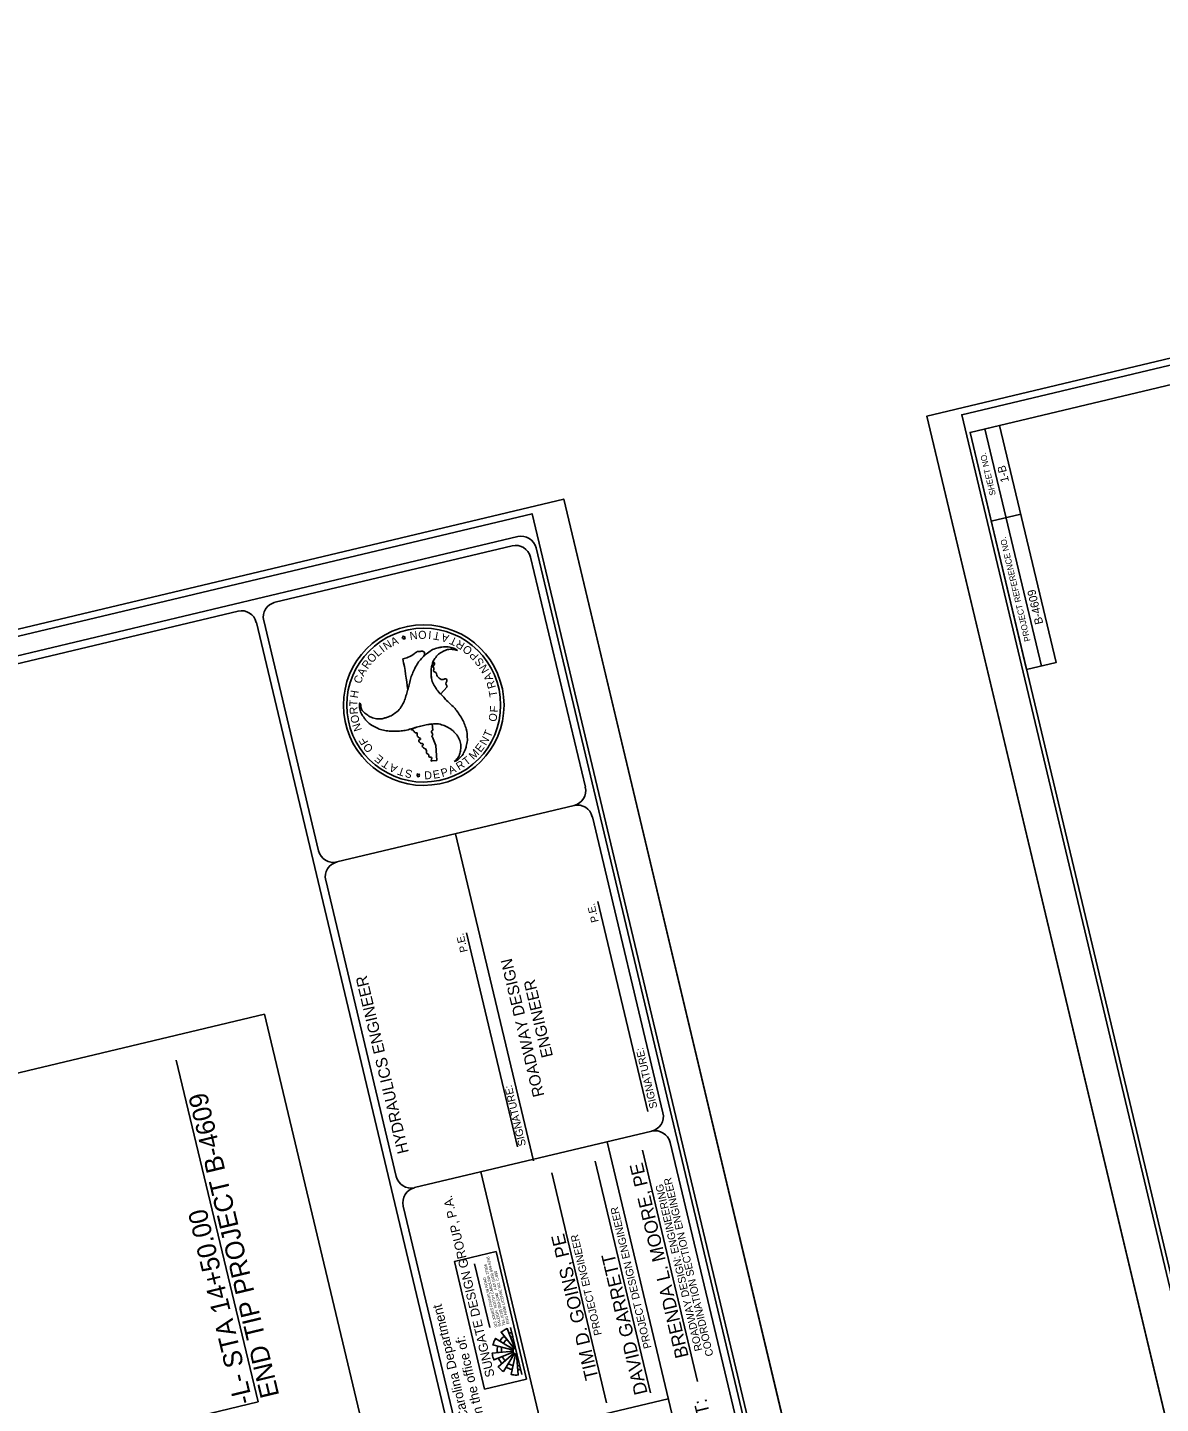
# Model space of a CAD drawing. Extents: x 1734738 to 1742883, y 698103 to 703125.
# Drawn here: x 1736174 to 1737661, y 700702 to 702508 of the extents above; entities that cross this region are included whole.
import ezdxf

# ---------------------------------------------------------------- set-up
doc = ezdxf.new("R2010")
doc.units = 0
for name, color, linetype in [('Exist Cultural Recreational Athletic Track', 7, 'Continuous'), ('Exist Map Preparation Border Sheet 1 CELL', 7, 'Continuous'), ('Exist Road Primary Interstate Shield CELL', 7, 'Continuous'), ('Exist Road Primary US Shield CELL', 7, 'Continuous'), ('Exist Road Primary US Structure Standard Bridge Number Label', 7, 'Continuous'), ('Exist Road Secondary Structure Pipe Number Label', 7, 'Continuous'), ('Exist Road Secondary Type 41 SR Number Label', 7, 'Continuous'), ('Exist Road Secondary Type 51 Divided Label', 7, 'Continuous'), ('Exist Road Secondary Type 51 Number Label', 7, 'Continuous')]:
    doc.layers.add(name, color=color, linetype=linetype)

msp = doc.modelspace()

# ---------------------------------------------------------------- linework, layer by layer
at = {"layer": 'Exist Cultural Recreational Athletic Track'}
for p in [(1736369.4, 701152.2), (1736188.7, 700634.5)]:
    msp.add_line(p, (1736477, 700703.7), dxfattribs=at)
at = {"layer": 'Exist Road Primary Interstate Shield CELL'}
for p, q in [((1737505.1, 701669.7), (1737430.9, 701981.1)), ((1737524.6, 701674.4), (1737450.3, 701985.7)), ((1737439.3, 701859.7), (1737478.2, 701869))]:
    msp.add_line(p, q, dxfattribs=at)
for points in [[(1737411.4, 701976.4), (1738106.9, 699058.2), (1740147.7, 699544.6), (1739452.2, 702462.8)], [(1737485.6, 701665.1), (1737411.4, 701976.4), (1737450.3, 701985.7), (1737524.6, 701674.4)]]:
    msp.add_lwpolyline(points, close=True, dxfattribs=at)
at = {"layer": 'Exist Road Primary US Shield CELL'}
msp.add_lwpolyline([(1735867.2, 699650.6), (1736804.2, 699873.9), (1736485.1, 701212.6), (1735736.8, 701034.2), (1735787.7, 700820.7), (1735599, 700775.7)], close=True, dxfattribs=at)
at = {"layer": 'Exist Road Primary US Structure Standard Bridge Number Label'}
for p, q in [((1737354.8, 701997.9), (1738135.7, 698721.7)), ((1737658.8, 698612.7), (1736878, 701888.9))]:
    msp.add_line(p, q, dxfattribs=at)
at = {"layer": 'Exist Road Secondary Structure Pipe Number Label'}
for points in [[(1740226.1, 699246.6), (1739453.3, 702488.8), (1737400.6, 701999.6), (1738173.4, 698757.4)], [(1737609.2, 698627.6), (1736836.4, 701869.7), (1734783.7, 701380.5), (1735556.5, 698138.3)]]:
    msp.add_lwpolyline(points, close=True, dxfattribs=at)
at = {"layer": 'Exist Road Secondary Type 41 SR Number Label'}
for points in [[(1740275.8, 699231.7), (1739494.9, 702508), (1737354.8, 701997.9), (1738135.7, 698721.7)], [(1734738, 701378.8), (1735518.8, 698102.6), (1737658.8, 698612.7), (1736878, 701888.9)]]:
    msp.add_lwpolyline(points, close=True, dxfattribs=at)
at = {"layer": 'Exist Road Secondary Type 51 Divided Label'}
for p, q in [((1737133, 698964.3), (1736474.5, 701727)), ((1736556.2, 701427.3), (1736484.3, 701729.3)), ((1736683.5, 701723.3), (1736683.5, 701723.3)), ((1736667.2, 701707.4), (1736665.6, 701706.6)), ((1736665.6, 701706.6), (1736667.3, 701706.2)), ((1736668.2, 701707.8), (1736667, 701709.2)), ((1736667, 701709.2), (1736667.2, 701707.4)), ((1736667.3, 701706.2), (1736667.5, 701704.4)), ((1736667.5, 701704.4), (1736668.4, 701706)), ((1736669.9, 701708.5), (1736668.2, 701707.8)), ((1736668.4, 701706), (1736670.2, 701705.7)), ((1736669, 701707), (1736669.9, 701708.5)), ((1736670.2, 701705.7), (1736669, 701707)), ((1736673.3, 701638.8), (1736673.3, 701638.8)), ((1736725.1, 701642.6), (1736716.4, 701632.8)), ((1736716.4, 701632.8), (1736716.4, 701632.8)), ((1736610, 701621), (1736610.2, 701620.9)), ((1736610, 701621), (1736610.2, 701620.9)), ((1736705.5, 701593.7), (1736706.2, 701585.4)), ((1736705.8, 701576.5), (1736710.3, 701565.5)), ((1736710.3, 701565.5), (1736711.6, 701545.5)), ((1736711.6, 701545.5), (1736705.3, 701545.1)), ((1736684.6, 701525.9), (1736686.2, 701526.7)), ((1736686.4, 701525.6), (1736684.6, 701525.9)), ((1736686.2, 701526.7), (1736686.1, 701528.5)), ((1736686.1, 701528.5), (1736687.3, 701527.1)), ((1736686.5, 701523.8), (1736686.4, 701525.6)), ((1736687.5, 701525.3), (1736686.5, 701523.8)), ((1736687.3, 701527.1), (1736689, 701527.9)), ((1736689.3, 701525), (1736687.5, 701525.3)), ((1736689, 701527.9), (1736688, 701526.3)), ((1736688, 701526.3), (1736689.3, 701525)), ((1736891.6, 701486.6), (1736580.3, 701412.5)), ((1736838.3, 701020.2), (1736735.9, 701449.5)), ((1736658.1, 700999.7), (1736565.5, 701388.4)), ((1736988.4, 701085.1), (1736922.9, 701360.4)), ((1736817.4, 701038.7), (1736750.5, 701319.3)), ((1736993.5, 701059.1), (1736682.3, 700984.9)), ((1737076.3, 700451.7), (1736934.9, 701045.1)), ((1737053.8, 700730.3), (1736981.3, 701034.3)), ((1736991.8, 700715.5), (1736919.4, 701019.5)), ((1736769.3, 701005.6), (1736910.7, 700412.3)), ((1736934.1, 700702.5), (1736862.2, 701004.3)), ((1736799.6, 700406.3), (1736667.4, 700960.8)), ((1736849.7, 700668.2), (1737015.3, 700707.7))]:
    msp.add_line(p, q, dxfattribs=at)
for points in [[(1736817.8, 701839.6), (1734813.9, 701362)], [(1736810.4, 701827.6), (1736499.1, 701753.4)], [(1736906.4, 701510.7), (1736834.5, 701812.7)], [(1737528.2, 698945.4), (1736841.9, 701824.8)], [(1736450.5, 701741.8), (1734825.9, 701354.6)], [(1737008.3, 701083.2), (1736915.7, 701471.8)], [(1737149.8, 700489.8), (1737017.6, 701044.3)]]:
    msp.add_lwpolyline(points, dxfattribs=at)
for centre, radius, start, end in [((1736814.9, 701808.1), 20, 13.4059, 103.4059), ((1736822.3, 701820.1), 20, 13.4059, 103.4059), ((1736455, 701722.3), 20, 13.4059, 103.4059), ((1736503.6, 701733.9), 20, 103.4059, 193.4059), ((1736694.2, 701618.4), 105.4, 95.827, 275.827), ((1736694.2, 701618.4), 105.4, 275.827, 95.827), ((1736694.2, 701618.4), 101, 275.827, 95.827), ((1736694.2, 701618.4), 101, 95.827, 275.827), ((1736121.5, 701571.6), 555.9, 6.9446, 11.1506), ((1736121.5, 701571.6), 555.9, 1.5055, 1.6051), ((1736886.9, 701506.1), 20, 283.4059, 13.4059), ((1736896.1, 701467.2), 20, 13.4059, 103.4059), ((1736575.7, 701431.9), 20, 193.4059, 283.4059), ((1736585, 701393), 20, 103.4059, 193.4059), ((1736988.8, 701078.5), 20, 283.4059, 13.4059), ((1736998.1, 701039.6), 20, 13.4059, 103.4059), ((1736677.5, 701004.3), 20, 193.4059, 283.4059), ((1736686.8, 700965.4), 20, 103.4059, 193.4059)]:
    msp.add_arc(centre, radius, start, end, dxfattribs=at)
for points in [[(1736738.5, 701690.1), (1736736.7, 701691.5), (1736730.2, 701694.2), (1736722.7, 701695), (1736722, 701695), (1736718, 701694.7), (1736713.3, 701693.7), (1736705.9, 701691.2), (1736699.2, 701686.8), (1736696.4, 701685), (1736693.8, 701682.3), (1736688.6, 701676.5), (1736684.6, 701670.4), (1736680.8, 701662.9), (1736677.9, 701656.1), (1736675.8, 701648.7), (1736674, 701641.3), (1736671.9, 701634.2), (1736669.8, 701626.7), (1736666.7, 701619.9), (1736666.4, 701619.3), (1736661.9, 701612.5), (1736656, 701607.4), (1736649.8, 701603.7), (1736646.5, 701602.4), (1736642.1, 701601.3), (1736639.6, 701600.5), (1736634.2, 701600.4), (1736626.9, 701601.8), (1736620.7, 701605), (1736615.7, 701609), (1736612.1, 701614.6), (1736610.2, 701620.9), (1736610, 701621)], [(1736666.9, 701679.1), (1736673.7, 701681.3), (1736681.6, 701685.8), (1736685.8, 701688.6), (1736689.7, 701689), (1736694.5, 701688.5), (1736695.4, 701684.1)], [(1736695.4, 701684.1), (1736693.8, 701682.3), (1736688.6, 701676.5), (1736684.6, 701670.4), (1736680.8, 701662.9), (1736677.9, 701656.1), (1736675.8, 701648.7), (1736674, 701641.3), (1736673.3, 701638.8)], [(1736734.3, 701544.3), (1736736.6, 701545.3), (1736742.1, 701549.6), (1736746.6, 701555.6), (1736746.8, 701556.2), (1736748.7, 701559.9), (1736750, 701564.3), (1736751.6, 701572.1), (1736751.1, 701580), (1736751, 701583.3), (1736749.9, 701587.1), (1736747.5, 701594.3), (1736744.3, 701600.8), (1736739.7, 701607.9), (1736735.3, 701613.8), (1736729.9, 701619.3), (1736724.3, 701624.6), (1736719.2, 701630), (1736713.9, 701635.6), (1736709.5, 701641.6), (1736709.1, 701642.3), (1736705.5, 701649.6), (1736704, 701657.1), (1736703.9, 701664.3), (1736704.3, 701668), (1736705.7, 701672.2), (1736706.2, 701674.8), (1736708.8, 701679.5), (1736713.6, 701685.1), (1736719.5, 701688.9), (1736725.6, 701691.2), (1736732.1, 701691.6), (1736738.5, 701690.1)], [(1736716.4, 701632.8), (1736713.9, 701635.6), (1736709.5, 701641.6), (1736709.1, 701642.3), (1736705.5, 701649.6), (1736704, 701657.1), (1736703.9, 701664.3), (1736704.3, 701668), (1736705.7, 701672.2), (1736706.2, 701674.6)], [(1736706.3, 701674.6), (1736708.2, 701673.8), (1736708.5, 701672.3), (1736706.6, 701669.3), (1736707.6, 701665.9), (1736706.9, 701664.3), (1736706.9, 701663.3), (1736710.3, 701661.1), (1736711.3, 701657.8), (1736715.9, 701652.8), (1736718.4, 701651.9), (1736723.3, 701652.9), (1736724.5, 701651.6), (1736724.4, 701650), (1736723.4, 701646.5), (1736725.1, 701642.6)], [(1736610.2, 701620.9), (1736609.9, 701618.4), (1736610.8, 701611.5), (1736613.8, 701604.6), (1736614.2, 701604.1), (1736616.5, 701600.7), (1736619.6, 701597.2), (1736625.6, 701592.1), (1736632.7, 701588.4), (1736635.7, 701587), (1736639.3, 701586), (1736646.9, 701584.5), (1736654.2, 701584), (1736662.6, 701584.4), (1736669.9, 701585.2), (1736677.3, 701587.2), (1736684.7, 701589.3), (1736692, 701591.1), (1736699.4, 701592.9), (1736706.9, 701593.7), (1736707.5, 701593.8), (1736715.7, 701593.2), (1736723, 701590.7), (1736729.3, 701587.2), (1736732.3, 701585), (1736735.4, 701581.7), (1736737.1, 701579.9), (1736740, 701575.4), (1736742.5, 701568.4), (1736742.8, 701561.3), (1736741.8, 701554.9), (1736738.9, 701549.1), (1736734.3, 701544.3)], [(1736677.1, 701587.2), (1736677.3, 701587.2), (1736684.7, 701589.3), (1736692, 701591.1), (1736699.4, 701592.9), (1736705.5, 701593.7)], [(1736705.3, 701545.1), (1736704.7, 701544.8), (1736703.9, 701545.8), (1736704.8, 701548.8), (1736703.4, 701550.2), (1736702.1, 701550), (1736700.8, 701551.1), (1736701, 701553.1), (1736698.4, 701554.7), (1736697.9, 701556.4), (1736697.5, 701559.9), (1736692.8, 701563.7), (1736692.4, 701565.4), (1736693.5, 701566), (1736693.6, 701567.1), (1736689.9, 701568.5), (1736689.4, 701568.9), (1736687.7, 701572.1), (1736688.3, 701573), (1736689.8, 701573.4), (1736690.1, 701573.9), (1736689.2, 701575), (1736687.2, 701576.2), (1736685.5, 701578.8), (1736685.5, 701581.9), (1736683, 701582.2), (1736680.2, 701585.5), (1736678.6, 701586.1), (1736677.1, 701586.2)], [(1736706.2, 701585.4), (1736704.8, 701584.5), (1736704.5, 701582.8), (1736705.9, 701580.7), (1736705.9, 701579.1), (1736704.8, 701577.1), (1736705.8, 701576.5)]]:
    msp.add_spline(points, degree=3, dxfattribs=at)
at = {"layer": 'Exist Road Secondary Type 51 Number Label'}
for p, q in [((1736780.8, 700801.1), (1736760.7, 700885.1)), ((1736822.9, 700739.8), (1736808.2, 700801.2)), ((1736814, 700774.3), (1736811.3, 700781)), ((1736796.7, 700775.4), (1736796.7, 700775.4)), ((1736811.5, 700770.1), (1736804.3, 700769.5)), ((1736811.6, 700771.5), (1736804.6, 700773.3)), ((1736811.8, 700769), (1736805, 700766.3)), ((1736805.9, 700776.4), (1736812.1, 700772.6)), ((1736812.5, 700767.8), (1736807.1, 700763)), ((1736813, 700773.7), (1736808.5, 700779.3)), ((1736809.6, 700760.9), (1736813.4, 700767)), ((1736810.4, 700776.9), (1736813, 700773.7)), ((1736814.7, 700766.5), (1736813.2, 700759.4)), ((1736815.9, 700766.4), (1736816.5, 700759.2)), ((1736800.9, 700757.7), (1736800.9, 700757.7)), ((1736813.6, 700761.3), (1736813.6, 700761.3)), ((1736817.5, 700748.2), (1736817.5, 700748.2))]:
    msp.add_line(p, q, dxfattribs=at)
for points in [[(1736774.2, 700720.5), (1736734.4, 700887.8), (1736789.2, 700900.9), (1736829.1, 700733.5)], [(1736813, 700773.7), (1736795.8, 700795.2), (1736797, 700796.1), (1736798.4, 700797), (1736800, 700798), (1736801.3, 700798.7), (1736803.8, 700799.8), (1736814, 700774.3)], [(1736811.6, 700771.5), (1736785, 700778.4), (1736785.6, 700780.5), (1736786.4, 700782.7), (1736787.1, 700784.2), (1736787.8, 700785.6), (1736788.6, 700786.9), (1736812.1, 700772.6)], [(1736794.2, 700783.5), (1736795, 700784.7), (1736795.9, 700785.9), (1736796.9, 700787.1), (1736798.4, 700788.6), (1736800, 700790), (1736803.4, 700785.7), (1736802.4, 700784.8), (1736801.2, 700783.6), (1736800.4, 700782.7), (1736799.8, 700781.8), (1736799, 700780.6)], [(1736806.3, 700793.6), (1736808.1, 700794.3), (1736809.7, 700794.7), (1736811, 700789.4), (1736809.7, 700789), (1736808.3, 700788.5)], [(1736811.8, 700769), (1736786.2, 700758.7), (1736785.6, 700760.4), (1736785, 700762.3), (1736784.7, 700763.9), (1736784.3, 700765.9), (1736784.1, 700767.7), (1736811.5, 700770.1)], [(1736790.7, 700768.3), (1736790.6, 700769.8), (1736790.6, 700771.6), (1736790.8, 700773.4), (1736791, 700775), (1736791.4, 700776.8), (1736796.8, 700775.4), (1736796.5, 700774.4), (1736796.3, 700773.1), (1736796.1, 700771.2), (1736796.1, 700770), (1736796.2, 700768.8)], [(1736813.4, 700767), (1736798.9, 700743.7), (1736797.4, 700744.6), (1736795.9, 700745.8), (1736794.5, 700746.9), (1736793.1, 700748.3), (1736791.8, 700749.6), (1736812.5, 700767.8)], [(1736796.8, 700754), (1736796, 700755), (1736794.8, 700756.6), (1736793.7, 700758.3), (1736792.9, 700759.9), (1736792.4, 700761.2), (1736797.5, 700763.3), (1736798, 700762.1), (1736798.6, 700761), (1736799.3, 700759.8), (1736800.1, 700758.7), (1736801, 700757.6)], [(1736815.9, 700766.4), (1736818.3, 700739), (1736816.6, 700738.9), (1736814.1, 700738.9), (1736812.6, 700739), (1736810.6, 700739.3), (1736809.1, 700739.6), (1736814.7, 700766.5)], [(1736816.5, 700766.5), (1736816.2, 700766.5), (1736815.9, 700766.4), (1736815.2, 700766.4), (1736814.7, 700766.5), (1736814.3, 700766.6), (1736813.9, 700766.7), (1736813.6, 700766.9), (1736813.4, 700767), (1736812.9, 700767.4), (1736812.5, 700767.8), (1736812.2, 700768.1), (1736812, 700768.4), (1736811.9, 700768.7), (1736811.8, 700769), (1736811.6, 700769.5), (1736811.5, 700770.1), (1736811.5, 700770.5), (1736811.5, 700770.8), (1736811.5, 700771.1), (1736811.6, 700771.5), (1736811.8, 700772.1), (1736812.1, 700772.6), (1736812.2, 700772.9), (1736812.5, 700773.2), (1736812.7, 700773.4), (1736813, 700773.7), (1736813.5, 700774), (1736814, 700774.3), (1736814.3, 700774.4), (1736814.6, 700774.4)], [(1736810.5, 700746.1), (1736808.9, 700746.4), (1736807.7, 700746.8), (1736806.3, 700747.3), (1736805.1, 700747.8), (1736803.8, 700748.5), (1736802.4, 700749.3), (1736805.3, 700754), (1736806.5, 700753.3), (1736807.5, 700752.8), (1736808.6, 700752.3), (1736809.8, 700751.9), (1736810.8, 700751.7), (1736811.6, 700751.5)], [(1736821.3, 700746.2), (1736820.3, 700746), (1736819, 700745.8), (1736817.7, 700745.6), (1736817.2, 700751.1), (1736818.2, 700751.2), (1736819.1, 700751.4), (1736820, 700751.6)]]:
    msp.add_lwpolyline(points, close=True, dxfattribs=at)
for start, end in [(103.3944, 283.3944), (283.3944, 103.3944)]:
    msp.add_arc((1736790.2, 700843.8), 0.176, start, end, dxfattribs=at)

# ---------------------------------------------------------------- texts
at = {"layer": 'Exist Cultural Recreational Athletic Track'}
for s, p in [('END TIP PROJECT B-4609', (1736504.7, 700712.2)), ('-L- STA 14+50.00', (1736469.7, 700703.5))]:
    msp.add_text(s, height=24.771, rotation=103.4845, dxfattribs=at).set_placement(p)
at = {"layer": 'Exist Map Preparation Border Sheet 1 CELL'}
for s, height, p in [('1-B', 10.8, (1737462.7, 701912.2)), ('B-4609   ', 10.8, (1737507.6, 701725.7)), ('BRENDA L. MOORE, PE', 17.5, (1737042.2, 700763.4)), ('TIM D. GOINS, PE    ', 17.5, (1736923.8, 700734.7)), ('     DAVID GARRETT          ', 17.5, (1736995.8, 700683.6))]:
    msp.add_text(s, height=height, rotation=103.4059, dxfattribs=at).set_placement(p)
at = {"layer": 'Exist Road Primary Interstate Shield CELL'}
for s, p in [('SHEET NO.', (1737445.4, 701894.6)), ('PROJECT REFERENCE NO.', (1737490.9, 701702.9))]:
    msp.add_text(s, height=8, rotation=103.4059, dxfattribs=at).set_placement(p)
at = {"layer": 'Exist Road Secondary Type 51 Divided Label'}
for s, height, rotation, p in [('N', 10.5, 31.7224, (1736644.9, 701690.2)), ('A', 10.5, 24.2904, (1736653.7, 701695.6)), ('N', 10.5, 188.0352, (1736685.1, 701715.7)), ('O', 10.5, 180.7872, (1736697.8, 701716)), ('I', 10.5, 175.6515, (1736704.6, 701715.6)), ('T', 10.5, 170.0016, (1736716.3, 701713.6)), ('A', 10.5, 162.9172, (1736728.2, 701710.1)), ('T', 10.5, 154.8302, (1736739.1, 701705.2)), ('R', 10.5, 148.7304, (1736749.1, 701699.2)), ('O', 10.5, 47.6455, (1736626.3, 701673)), ('L', 10.5, 41.4118, (1736633.9, 701681.3)), ('I', 10.5, 37.4225, (1736640.8, 701687.2)), ('O', 10.5, 141.5413, (1736759.1, 701691.4)), ('P', 10.5, 134.8493, (1736767.1, 701683.5)), ('A', 10.5, 61.1291, (1736615.3, 701655.4)), ('R', 10.5, 54.7651, (1736620.5, 701664.9)), ('S', 10.5, 127.6574, (1736774.3, 701674.3)), ('N', 10.5, 120.447, (1736780.5, 701664.2)), ('C', 10.5, 68.6261, (1736611.4, 701645.6)), ('A', 10.5, 113.4153, (1736785.6, 701652.9)), ('R', 10.5, 106.6622, (1736789.1, 701641.8)), ('H', 10.5, 80.9684, (1736607.5, 701627)), ('T', 10.5, 99.7056, (1736791.2, 701630.1)), ('T', 10.5, 88.0532, (1736607.1, 701616.7)), ('R', 10.5, 94.7028, (1736607.9, 701606.7)), ('F', 10.5, 86.7963, (1736791.4, 701608.6)), ('O', 10.5, 101.3127, (1736610.1, 701595.8)), ('N', 10.5, 108.8108, (1736613.3, 701586.1)), ('O', 10.5, 79.6311, (1736789.3, 701596)), ('N', 10.5, 59.4854, (1736775.8, 701564.7)), ('T', 10.5, 66.3274, (1736781.7, 701574.9)), ('F', 10.5, 120.8978, (1736621.9, 701569.9)), ('O', 10.5, 128.0446, (1736628.7, 701561.1)), ('M', 10.5, 45.0471, (1736759.7, 701546)), ('E', 10.5, 52.5139, (1736769, 701555.6)), ('E', 10.5, 139.984, (1736642.3, 701548.4)), ('T', 10.5, 147.0996, (1736651, 701542.8)), ('A', 10.5, 154.1548, (1736660.7, 701538)), ('A', 10.5, 24.0929, (1736729.2, 701527.2)), ('R', 10.5, 31.1615, (1736740.5, 701532.4)), ('T', 10.5, 37.8121, (1736750.3, 701538.5)), ('T', 10.5, 161.2071, (1736670.4, 701534.6)), ('S', 10.5, 167.5833, (1736680.2, 701532.4)), ('D', 10.5, 3.68, (1736695.2, 701520.8)), ('E', 10.5, 9.9679, (1736707.2, 701521.6)), ('P', 10.5, 17.5003, (1736718.5, 701523.8)), ('P.E.', 10, 103.4059, (1736924.1, 701334.3)), ('P.E.', 10, 103.4059, (1736752.1, 701295.1)), ('ROADWAY DESIGN', 14.999, 103.4059, (1736852.7, 701105.9)), (' HYDRAULICS ENGINEER', 15, 103.4059, (1736676.1, 701026)), ('ENGINEER', 15, 103.4059, (1736864, 701157.6)), ('SIGNATURE:', 10, 103.4059, (1737001.1, 701090)), ('SIGNATURE:', 10, 103.4059, (1736828.6, 701040.8)), ('COORDINATION SECTION ENGINEER', 9.999, 103.4059, (1737074.6, 700764.8)), ('ROADWAY DESIGN: ENGINEERING', 9.999, 103.4059, (1737060.1, 700771.6)), ('PROJECT DESIGN ENGINEER', 9.999, 103.4059, (1736993.2, 700774.9)), ('PROJECT ENGINEER', 9.999, 103.4059, (1736928.1, 700792.2)), ('Prepared for the North Carolina Department', 12.515, 103.3944, (1736792.9, 700516.1)), ('of Transportation in the office of:', 12.515, 103.3944, (1736803.2, 700558.1)), ('NCDOT CONTACT:', 17.5, 103.4059, (1737113.6, 700505.4))]:
    msp.add_text(s, height=height, rotation=rotation, dxfattribs=at).set_placement(p)
at = {"layer": 'Exist Road Secondary Type 51 Number Label'}
for s, height, p in [('SUNGATE DESIGN GROUP, P.A.', 11.929, (1736787.5, 700737.7)), ('TEL (919) 859-2243   FAX (919) 859-6258', 3.585, (1736801.6, 700804.1)), ('RALEIGH, NORTH CAROLINA 27606', 3.585, (1736796.2, 700803.2)), ('ENG FIRM LICENSE NO. C-890', 3.585, (1736806.7, 700806.3)), ('915 JONES FRANKLIN ROAD', 3.585, (1736791.1, 700801.9))]:
    msp.add_text(s, height=height, rotation=103.3944, dxfattribs=at).set_placement(p)

doc.saveas('drawing.dxf')
